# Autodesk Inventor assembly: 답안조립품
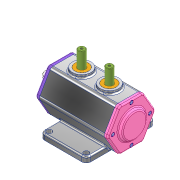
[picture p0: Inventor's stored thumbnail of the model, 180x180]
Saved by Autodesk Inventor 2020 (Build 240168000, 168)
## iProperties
Created: 2021-06
Part Number: 답안조립품
Document SubType Name: Assembly
Designer: Administrator
Author: Administrator
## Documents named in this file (11)
- C:\Users\Administrator\Desktop\710606V1007\답안조립품.iam
- C:\Users\Administrator\Desktop\710606V1007\본체.ipt
- C:\Users\Administrator\Desktop\710606V1007\편심축.ipt
- C:\Users\Administrator\Desktop\710606V1007\베어링 6203.ipt
- C:\Users\Administrator\Desktop\710606V1007\베어링 6302.ipt
- C:\Users\Administrator\Desktop\710606V1007\부시.ipt
- C:\Users\Administrator\Desktop\710606V1007\슬라이더.ipt
- C:\Users\Administrator\Desktop\710606V1007\뒷커버.ipt
- C:\Users\Administrator\Desktop\710606V1007\앞커버.ipt
- C:\Users\Administrator\Desktop\710606V1007\오일실.ipt
- C:\Users\Administrator\Desktop\710606V1007\볼트 M4.ipt
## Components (10 placed, 3 different names)
1. 7-베어링 6203:1
2. 8-오일실:1
3. 9-M4-소켓머리:2
4. 9-M4-소켓머리:3
5. 9-M4-소켓머리:4
6. 9-M4-소켓머리:5
7. 9-M4-소켓머리:1
8. 9-M4-소켓머리:6
9. 9-M4-소켓머리:7
10. 9-M4-소켓머리:8
